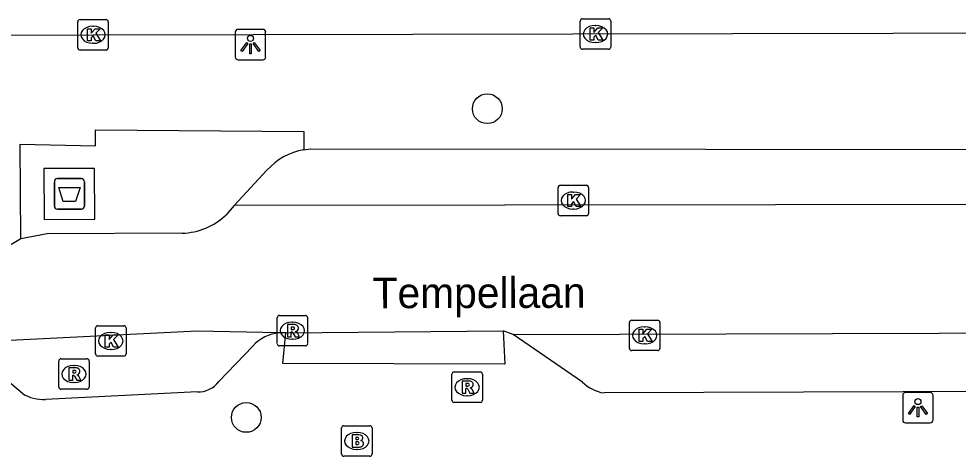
# Model space of a CAD drawing. Extents: x 160732 to 162105, y 387428 to 388479.
# Drawn here: x 161057.8 to 161088.62, y 388326.06 to 388340.41 of the extents above; entities that cross this region are included whole.
import ezdxf

# ---------------------------------------------------------------- set-up
doc = ezdxf.new("R2010")
doc.units = 0
for name, color, linetype in [('IMGEO_Afval_apart_plaats', 7, 'Continuous'), ('IMGEO_Boom', 7, 'Continuous'), ('IMGEO_Brandkraan', 7, 'Continuous'), ('IMGEO_Kolk', 7, 'Continuous'), ('IMGEO_Lichtpunt', 7, 'Continuous'), ('IMGEO_Openbare_ruimte_label', 7, 'Continuous'), ('IMGEO_Parkeervlak_open', 7, 'Continuous'), ('IMGEO_Rijbaan_lokaal_open', 7, 'Continuous'), ('IMGEO_Rijbaan_regionaal_gesloten', 7, 'Continuous'), ('IMGEO_Rioolput', 7, 'Continuous'), ('IMGEO_Voetpad_gesloten', 7, 'Continuous'), ('IMGEO_Voetpad_open', 7, 'Continuous')]:
    doc.layers.add(name, color=color, linetype=linetype)

msp = doc.modelspace()

# ---------------------------------------------------------------- linework, layer by layer
at = {"layer": 'IMGEO_Afval_apart_plaats'}
for p, q in [((161058.967, 388334.266), (161058.967, 388335.066)), ((161058.967, 388335.066), (161058.967, 388334.266)), ((161059.067, 388335.166), (161059.857, 388335.166)), ((161059.857, 388335.166), (161059.067, 388335.166)), ((161059.957, 388335.066), (161059.957, 388334.266)), ((161059.957, 388334.266), (161059.957, 388335.066)), ((161059.857, 388334.166), (161059.067, 388334.166)), ((161059.067, 388334.166), (161059.857, 388334.166))]:
    msp.add_line(p, q, dxfattribs=at)
msp.add_lwpolyline([(161059.11, 388334.88), (161059.814, 388334.88), (161059.665, 388334.41), (161059.259, 388334.41), (161059.11, 388334.88)], dxfattribs=at)
for centre, start, end in [((161059.067, 388335.066), 90, 180), ((161059.067, 388335.066), 90, 180), ((161059.857, 388335.066), 0, 90), ((161059.857, 388335.066), 360, 90), ((161059.067, 388334.266), 180, 270), ((161059.067, 388334.266), 180, 270), ((161059.857, 388334.266), 270, 0), ((161059.857, 388334.266), 270, 0)]:
    msp.add_arc(centre, 0.1, start, end, dxfattribs=at)
at = {"layer": 'IMGEO_Boom'}
for centre in [(161073.173, 388337.461), (161065.264, 388327.33)]:
    msp.add_circle(centre, 0.489, dxfattribs=at)
at = {"layer": 'IMGEO_Brandkraan'}
for p, q in [((161068.39, 388326.131), (161068.39, 388326.983)), ((161068.465, 388327.057), (161069.317, 388327.057)), ((161069.391, 388326.983), (161069.391, 388326.131)), ((161068.878, 388326.837), (161068.903, 388326.837)), ((161069.317, 388326.057), (161068.465, 388326.057)), ((161068.901, 388326.277), (161068.876, 388326.277))]:
    msp.add_line(p, q, dxfattribs=at)
for points in [[(161068.39, 388326.131), (161068.39, 388326.983)], [(161068.465, 388327.057), (161069.317, 388327.057)], [(161069.391, 388326.983), (161069.391, 388326.131)], [(161068.738, 388326.757), (161068.738, 388326.357), (161068.951, 388326.357)], [(161068.969, 388326.757), (161068.738, 388326.757)], [(161068.917, 388326.676), (161068.863, 388326.676), (161068.863, 388326.6)], [(161068.863, 388326.6), (161068.916, 388326.6)], [(161068.925, 388326.524), (161068.863, 388326.524), (161068.863, 388326.443)], [(161068.863, 388326.443), (161068.925, 388326.443)], [(161069.317, 388326.057), (161068.465, 388326.057)]]:
    msp.add_lwpolyline(points, dxfattribs=at)
for centre, radius, start, end in [((161068.467, 388326.981), 0.0765, 91.552, 178.448), ((161068.467, 388326.981), 0.0765, 91.552, 178.448), ((161069.315, 388326.981), 0.0765, 1.552, 88.448), ((161069.315, 388326.981), 0.0765, 1.552, 88.448), ((161068.918, 388326.638), 0.0379, 267.8285, 90.9355), ((161068.973, 388326.612), 0.145, 59.4692, 91.5367), ((161068.998, 388326.659), 0.0922, 285.5137, 58.1501), ((161068.926, 388326.483), 0.0404, 269.8759, 90.5077), ((161068.957, 388326.608), 0.251, 268.6676, 293.5347), ((161069.003, 388326.467), 0.105, 301.3115, 78.989), ((161068.467, 388326.133), 0.0765, 181.552, 268.448), ((161068.467, 388326.133), 0.0765, 181.552, 268.448), ((161069.315, 388326.133), 0.0765, 271.552, 358.448), ((161069.315, 388326.133), 0.0765, 271.552, 358.448)]:
    msp.add_arc(centre, radius, start, end, dxfattribs=at)
for centre, major_axis, ratio, start_param, end_param in [((161068.877, 388326.557), (-0.387, 0.002), 0.722429, 4.712389, 7.853982), ((161068.902, 388326.557), (-0.39, 0.002), 0.717154, 1.570796, 4.712389)]:
    msp.add_ellipse(centre, major_axis=major_axis, ratio=ratio, start_param=start_param, end_param=end_param, dxfattribs=at)
at = {"layer": 'IMGEO_Kolk'}
for p, q in [((161059.735, 388339.461), (161059.735, 388340.313)), ((161059.81, 388340.387), (161060.662, 388340.387)), ((161060.736, 388340.313), (161060.736, 388339.461)), ((161076.221, 388339.485), (161076.221, 388340.337)), ((161076.296, 388340.411), (161077.148, 388340.411)), ((161076.709, 388340.191), (161076.734, 388340.191)), ((161077.222, 388340.337), (161077.222, 388339.485)), ((161060.223, 388340.167), (161060.248, 388340.167)), ((161060.246, 388339.607), (161060.221, 388339.607)), ((161076.732, 388339.631), (161076.707, 388339.631)), ((161060.662, 388339.387), (161059.81, 388339.387)), ((161077.148, 388339.411), (161076.296, 388339.411)), ((161075.57, 388334.946), (161076.422, 388334.946)), ((161075.495, 388334.02), (161075.495, 388334.872)), ((161075.983, 388334.726), (161076.008, 388334.726)), ((161076.496, 388334.872), (161076.496, 388334.02)), ((161076.006, 388334.166), (161075.981, 388334.166)), ((161076.422, 388333.946), (161075.57, 388333.946)), ((161060.393, 388330.34), (161061.245, 388330.34)), ((161077.836, 388329.595), (161077.836, 388330.447)), ((161077.911, 388330.521), (161078.763, 388330.521)), ((161078.837, 388330.447), (161078.837, 388329.595)), ((161060.318, 388329.414), (161060.318, 388330.266)), ((161060.806, 388330.12), (161060.831, 388330.12)), ((161061.319, 388330.266), (161061.319, 388329.414)), ((161078.324, 388330.301), (161078.349, 388330.301)), ((161078.347, 388329.741), (161078.322, 388329.741)), ((161060.829, 388329.56), (161060.804, 388329.56)), ((161078.763, 388329.521), (161077.911, 388329.521)), ((161061.245, 388329.34), (161060.393, 388329.34))]:
    msp.add_line(p, q, dxfattribs=at)
for points in [[(161059.735, 388339.461), (161059.735, 388340.313)], [(161059.81, 388340.387), (161060.662, 388340.387)], [(161060.736, 388340.313), (161060.736, 388339.461)], [(161076.221, 388339.485), (161076.221, 388340.337)], [(161076.296, 388340.411), (161077.148, 388340.411)], [(161077.222, 388340.337), (161077.222, 388339.485)], [(161060.056, 388340.087), (161060.179, 388340.087), (161060.179, 388339.936), (161060.309, 388340.087), (161060.473, 388340.087), (161060.327, 388339.936), (161060.48, 388339.687), (161060.328, 388339.687), (161060.243, 388339.851), (161060.179, 388339.784), (161060.179, 388339.687), (161060.056, 388339.687), (161060.056, 388340.087)], [(161076.542, 388340.111), (161076.665, 388340.111), (161076.665, 388339.96), (161076.795, 388340.111), (161076.959, 388340.111), (161076.813, 388339.96), (161076.966, 388339.711), (161076.814, 388339.711), (161076.729, 388339.875), (161076.665, 388339.808), (161076.665, 388339.711), (161076.542, 388339.711), (161076.542, 388340.111)], [(161060.662, 388339.387), (161059.81, 388339.387)], [(161077.148, 388339.411), (161076.296, 388339.411)], [(161075.57, 388334.946), (161076.422, 388334.946)], [(161075.495, 388334.02), (161075.495, 388334.872)], [(161075.816, 388334.646), (161075.939, 388334.646), (161075.939, 388334.495), (161076.069, 388334.646), (161076.233, 388334.646), (161076.087, 388334.495), (161076.24, 388334.246), (161076.088, 388334.246), (161076.003, 388334.41), (161075.939, 388334.343), (161075.939, 388334.246), (161075.816, 388334.246), (161075.816, 388334.646)], [(161076.496, 388334.872), (161076.496, 388334.02)], [(161076.422, 388333.946), (161075.57, 388333.946)], [(161060.393, 388330.34), (161061.245, 388330.34)], [(161077.836, 388329.595), (161077.836, 388330.447)], [(161077.911, 388330.521), (161078.763, 388330.521)], [(161078.837, 388330.447), (161078.837, 388329.595)], [(161060.318, 388329.414), (161060.318, 388330.266)], [(161060.639, 388330.04), (161060.762, 388330.04), (161060.762, 388329.889), (161060.892, 388330.04), (161061.056, 388330.04), (161060.91, 388329.889), (161061.063, 388329.64), (161060.911, 388329.64), (161060.826, 388329.804), (161060.762, 388329.737), (161060.762, 388329.64), (161060.639, 388329.64), (161060.639, 388330.04)], [(161061.319, 388330.266), (161061.319, 388329.414)], [(161078.157, 388330.221), (161078.28, 388330.221), (161078.28, 388330.07), (161078.41, 388330.221), (161078.574, 388330.221), (161078.428, 388330.07), (161078.581, 388329.821), (161078.429, 388329.821), (161078.344, 388329.985), (161078.28, 388329.918), (161078.28, 388329.821), (161078.157, 388329.821), (161078.157, 388330.221)], [(161078.763, 388329.521), (161077.911, 388329.521)], [(161061.245, 388329.34), (161060.393, 388329.34)]]:
    msp.add_lwpolyline(points, dxfattribs=at)
for centre, start, end in [((161059.812, 388340.311), 91.552, 178.448), ((161059.812, 388340.311), 91.552, 178.448), ((161060.66, 388340.311), 1.552, 88.448), ((161060.66, 388340.311), 1.552, 88.448), ((161076.298, 388340.335), 91.552, 178.448), ((161076.298, 388340.335), 91.552, 178.448), ((161077.146, 388340.335), 1.552, 88.448), ((161077.146, 388340.335), 1.552, 88.448), ((161059.812, 388339.463), 181.552, 268.448), ((161059.812, 388339.463), 181.552, 268.448), ((161060.66, 388339.463), 271.552, 358.448), ((161060.66, 388339.463), 271.552, 358.448), ((161076.298, 388339.487), 181.552, 268.448), ((161076.298, 388339.487), 181.552, 268.448), ((161077.146, 388339.487), 271.552, 358.448), ((161077.146, 388339.487), 271.552, 358.448), ((161075.572, 388334.87), 91.552, 178.448), ((161075.572, 388334.87), 91.552, 178.448), ((161076.42, 388334.87), 1.552, 88.448), ((161076.42, 388334.87), 1.552, 88.448), ((161075.572, 388334.022), 181.552, 268.448), ((161075.572, 388334.022), 181.552, 268.448), ((161076.42, 388334.022), 271.552, 358.448), ((161076.42, 388334.022), 271.552, 358.448), ((161060.395, 388330.264), 91.552, 178.448), ((161060.395, 388330.264), 91.552, 178.448), ((161061.243, 388330.264), 1.552, 88.448), ((161061.243, 388330.264), 1.552, 88.448), ((161077.913, 388330.445), 91.552, 178.448), ((161077.913, 388330.445), 91.552, 178.448), ((161078.761, 388330.445), 1.552, 88.448), ((161078.761, 388330.445), 1.552, 88.448), ((161060.395, 388329.416), 181.552, 268.448), ((161060.395, 388329.416), 181.552, 268.448), ((161061.243, 388329.416), 271.552, 358.448), ((161061.243, 388329.416), 271.552, 358.448), ((161077.913, 388329.597), 181.552, 268.448), ((161077.913, 388329.597), 181.552, 268.448), ((161078.761, 388329.597), 271.552, 358.448), ((161078.761, 388329.597), 271.552, 358.448)]:
    msp.add_arc(centre, 0.0765, start, end, dxfattribs=at)
for centre, major_axis, ratio, start_param, end_param in [((161076.708, 388339.911), (-0.387, 0.002), 0.722429, 4.712389, 7.853982), ((161076.733, 388339.911), (-0.39, 0.002), 0.717154, 1.570796, 4.712389), ((161060.222, 388339.887), (-0.387, 0.002), 0.722429, 4.712389, 7.853982), ((161060.247, 388339.887), (-0.39, 0.002), 0.717154, 1.570796, 4.712389), ((161075.982, 388334.446), (-0.387, 0.002), 0.722429, 4.712389, 7.853982), ((161076.007, 388334.446), (-0.39, 0.002), 0.717154, 1.570796, 4.712389), ((161060.805, 388329.84), (-0.387, 0.002), 0.722429, 4.712389, 7.853982), ((161060.83, 388329.84), (-0.39, 0.002), 0.717154, 1.570796, 4.712389), ((161078.323, 388330.021), (-0.387, 0.002), 0.722429, 4.712389, 7.853982), ((161078.348, 388330.021), (-0.39, 0.002), 0.717154, 1.570796, 4.712389)]:
    msp.add_ellipse(centre, major_axis=major_axis, ratio=ratio, start_param=start_param, end_param=end_param, dxfattribs=at)
at = {"layer": 'IMGEO_Lichtpunt'}
for p, q in [((161064.904, 388339.968), (161064.904, 388339.161)), ((161064.904, 388339.968), (161064.904, 388339.161)), ((161065.806, 388340.063), (161064.998, 388340.063)), ((161065.806, 388340.063), (161064.998, 388340.063)), ((161065.9, 388339.161), (161065.9, 388339.968)), ((161065.9, 388339.161), (161065.9, 388339.968)), ((161064.998, 388339.067), (161065.806, 388339.067)), ((161064.998, 388339.067), (161065.806, 388339.067)), ((161086.802, 388328.052), (161086.802, 388327.245)), ((161086.802, 388328.052), (161086.802, 388327.245)), ((161087.704, 388328.147), (161086.896, 388328.147)), ((161087.704, 388328.147), (161086.896, 388328.147)), ((161087.798, 388327.245), (161087.798, 388328.052)), ((161087.798, 388327.245), (161087.798, 388328.052)), ((161086.896, 388327.151), (161087.704, 388327.151)), ((161086.896, 388327.151), (161087.704, 388327.151))]:
    msp.add_line(p, q, dxfattribs=at)
for points in [[(161065.278, 388339.632), (161065.317, 388339.604), (161065.129, 388339.342), (161065.091, 388339.369), (161065.278, 388339.632)], [(161065.38, 388339.584), (161065.427, 388339.584), (161065.427, 388339.262), (161065.38, 388339.262), (161065.38, 388339.584)], [(161065.49, 388339.604), (161065.528, 388339.631), (161065.715, 388339.369), (161065.676, 388339.341), (161065.49, 388339.604)], [(161087.176, 388327.716), (161087.215, 388327.688), (161087.027, 388327.426), (161086.989, 388327.453), (161087.176, 388327.716)], [(161087.278, 388327.668), (161087.325, 388327.668), (161087.325, 388327.346), (161087.278, 388327.346), (161087.278, 388327.668)], [(161087.388, 388327.688), (161087.426, 388327.715), (161087.613, 388327.453), (161087.574, 388327.425), (161087.388, 388327.688)]]:
    msp.add_lwpolyline(points, dxfattribs=at)
for centre in [(161065.403, 388339.766), (161087.301, 388327.85)]:
    msp.add_circle(centre, 0.0994, dxfattribs=at)
for centre, start, end in [((161064.998, 388339.968), 90, 180), ((161064.998, 388339.968), 90, 180), ((161065.806, 388339.968), 0, 90), ((161065.806, 388339.968), 0, 90), ((161064.998, 388339.161), 180, 270), ((161064.998, 388339.161), 180, 270), ((161065.806, 388339.161), 270, 0), ((161065.806, 388339.161), 270, 360), ((161086.896, 388328.052), 90, 180), ((161086.896, 388328.052), 90, 180), ((161087.704, 388328.052), 0, 90), ((161087.704, 388328.052), 0, 90), ((161086.896, 388327.245), 180, 270), ((161086.896, 388327.245), 180, 270), ((161087.704, 388327.245), 270, 0), ((161087.704, 388327.245), 270, 360)]:
    msp.add_arc(centre, 0.0946, start, end, dxfattribs=at)
at = {"layer": 'IMGEO_Parkeervlak_open'}
msp.add_lwpolyline([(161067.152, 388336.115), (161067.357, 388336.139), (161106.269, 388336.114)], dxfattribs=at)
at = {"layer": 'IMGEO_Rijbaan_lokaal_open'}
for points in [[(161109.259, 388334.338), (161064.865, 388334.284)], [(161064.865, 388334.284), (161064.601, 388333.978)], [(161057.87, 388333.189), (161057.295, 388332.853)], [(161063.16, 388333.374), (161058.732, 388333.358), (161057.87, 388333.189)], [(161066.347, 388330.105), (161063.655, 388330.157), (161055.964, 388329.781)], [(161066.562, 388330.109), (161066.347, 388330.105)], [(161066.562, 388330.109), (161073.696, 388330.176)], [(161074.021, 388330.052), (161073.696, 388330.176)], [(161074.021, 388330.052), (161119.444, 388330.198)]]:
    msp.add_lwpolyline(points, dxfattribs=at)
msp.add_arc((161063.084, 388335.575), 2.203, 271.9681, 313.5142, dxfattribs=at)
at = {"layer": 'IMGEO_Rijbaan_regionaal_gesloten'}
msp.add_lwpolyline([(161054.982, 388339.878), (161144.197, 388340.064)], dxfattribs=at)
at = {"layer": 'IMGEO_Rioolput'}
for p, q in [((161066.352, 388330.676), (161067.204, 388330.676)), ((161066.277, 388329.75), (161066.277, 388330.602)), ((161066.765, 388330.456), (161066.79, 388330.456)), ((161067.278, 388330.602), (161067.278, 388329.75)), ((161066.788, 388329.896), (161066.763, 388329.896)), ((161067.204, 388329.676), (161066.352, 388329.676)), ((161059.11, 388328.329), (161059.11, 388329.181)), ((161059.185, 388329.255), (161060.037, 388329.255)), ((161060.111, 388329.181), (161060.111, 388328.329)), ((161059.598, 388329.035), (161059.623, 388329.035)), ((161072.085, 388328.821), (161072.937, 388328.821)), ((161059.621, 388328.475), (161059.596, 388328.475)), ((161072.01, 388327.895), (161072.01, 388328.747)), ((161072.498, 388328.601), (161072.523, 388328.601)), ((161073.011, 388328.747), (161073.011, 388327.895)), ((161060.037, 388328.255), (161059.185, 388328.255)), ((161072.521, 388328.041), (161072.496, 388328.041)), ((161072.937, 388327.821), (161072.085, 388327.821))]:
    msp.add_line(p, q, dxfattribs=at)
for points in [[(161066.352, 388330.676), (161067.204, 388330.676)], [(161066.277, 388329.75), (161066.277, 388330.602)], [(161066.866, 388330.374), (161066.614, 388330.376), (161066.614, 388329.976)], [(161067.278, 388330.602), (161067.278, 388329.75)], [(161066.614, 388329.976), (161066.738, 388329.976), (161066.738, 388330.138), (161066.749, 388330.138)], [(161066.792, 388330.295), (161066.738, 388330.295), (161066.738, 388330.214)], [(161066.738, 388330.214), (161066.79, 388330.214)], [(161066.796, 388330.109), (161066.867, 388329.976), (161067.007, 388329.976), (161066.942, 388330.102)], [(161067.204, 388329.676), (161066.352, 388329.676)], [(161059.11, 388328.329), (161059.11, 388329.181)], [(161059.185, 388329.255), (161060.037, 388329.255)], [(161060.111, 388329.181), (161060.111, 388328.329)], [(161059.699, 388328.953), (161059.447, 388328.955), (161059.447, 388328.555)], [(161059.625, 388328.874), (161059.571, 388328.874), (161059.571, 388328.793)], [(161059.571, 388328.793), (161059.623, 388328.793)], [(161072.085, 388328.821), (161072.937, 388328.821)], [(161059.447, 388328.555), (161059.571, 388328.555), (161059.571, 388328.717), (161059.582, 388328.717)], [(161059.629, 388328.688), (161059.7, 388328.555), (161059.84, 388328.555), (161059.775, 388328.681)], [(161072.01, 388327.895), (161072.01, 388328.747)], [(161072.599, 388328.519), (161072.347, 388328.521), (161072.347, 388328.121)], [(161073.011, 388328.747), (161073.011, 388327.895)], [(161060.037, 388328.255), (161059.185, 388328.255)], [(161072.347, 388328.121), (161072.471, 388328.121), (161072.471, 388328.283), (161072.482, 388328.283)], [(161072.525, 388328.44), (161072.471, 388328.44), (161072.471, 388328.359)], [(161072.471, 388328.359), (161072.523, 388328.359)], [(161072.529, 388328.254), (161072.6, 388328.121), (161072.74, 388328.121), (161072.675, 388328.247)], [(161072.937, 388327.821), (161072.085, 388327.821)]]:
    msp.add_lwpolyline(points, dxfattribs=at)
for centre, radius, start, end in [((161066.354, 388330.6), 0.0765, 91.552, 178.448), ((161066.354, 388330.6), 0.0765, 91.552, 178.448), ((161067.202, 388330.6), 0.0765, 1.552, 88.448), ((161067.202, 388330.6), 0.0765, 1.552, 88.448), ((161066.865, 388330.264), 0.109, 350.3612, 89.416), ((161066.748, 388330.085), 0.0533, 26.0293, 88.6989), ((161066.774, 388330.403), 0.19, 274.7715, 282.9687), ((161066.798, 388330.199), 0.0964, 77.0061, 93.1865), ((161066.812, 388330.256), 0.0378, 276.6634, 79.6772), ((161066.863, 388330.264), 0.112, 277.5842, 350.9817), ((161066.847, 388330.049), 0.108, 29.5134, 73.7905), ((161066.354, 388329.752), 0.0765, 181.552, 268.448), ((161066.354, 388329.752), 0.0765, 181.552, 268.448), ((161067.202, 388329.752), 0.0765, 271.552, 358.448), ((161067.202, 388329.752), 0.0765, 271.552, 358.448), ((161059.187, 388329.179), 0.0765, 91.552, 178.448), ((161059.187, 388329.179), 0.0765, 91.552, 178.448), ((161060.035, 388329.179), 0.0765, 1.552, 88.448), ((161060.035, 388329.179), 0.0765, 1.552, 88.448), ((161059.607, 388328.982), 0.19, 274.7715, 282.9687), ((161059.631, 388328.778), 0.0964, 77.0061, 93.1865), ((161059.645, 388328.835), 0.0378, 276.6634, 79.6772), ((161059.698, 388328.843), 0.109, 350.3612, 89.416), ((161059.696, 388328.843), 0.112, 277.5842, 350.9817), ((161072.087, 388328.745), 0.0765, 91.552, 178.448), ((161072.087, 388328.745), 0.0765, 91.552, 178.448), ((161072.935, 388328.745), 0.0765, 1.552, 88.448), ((161072.935, 388328.745), 0.0765, 1.552, 88.448), ((161059.581, 388328.664), 0.0533, 26.0293, 88.6989), ((161059.68, 388328.628), 0.108, 29.5134, 73.7905), ((161072.598, 388328.409), 0.109, 350.3612, 89.416), ((161059.187, 388328.331), 0.0765, 181.552, 268.448), ((161059.187, 388328.331), 0.0765, 181.552, 268.448), ((161060.035, 388328.331), 0.0765, 271.552, 358.448), ((161060.035, 388328.331), 0.0765, 271.552, 358.448), ((161072.481, 388328.23), 0.0533, 26.0293, 88.6989), ((161072.507, 388328.548), 0.19, 274.7715, 282.9687), ((161072.531, 388328.344), 0.0964, 77.0061, 93.1865), ((161072.545, 388328.401), 0.0378, 276.6634, 79.6772), ((161072.596, 388328.409), 0.112, 277.5842, 350.9817), ((161072.58, 388328.194), 0.108, 29.5134, 73.7905), ((161072.087, 388327.897), 0.0765, 181.552, 268.448), ((161072.087, 388327.897), 0.0765, 181.552, 268.448), ((161072.935, 388327.897), 0.0765, 271.552, 358.448), ((161072.935, 388327.897), 0.0765, 271.552, 358.448)]:
    msp.add_arc(centre, radius, start, end, dxfattribs=at)
for centre, major_axis, ratio, start_param, end_param in [((161066.764, 388330.176), (-0.387, 0.002), 0.722429, 4.712389, 7.853982), ((161066.789, 388330.176), (-0.39, 0.002), 0.717154, 1.570796, 4.712389), ((161059.597, 388328.755), (-0.387, 0.002), 0.722429, 4.712389, 7.853982), ((161059.622, 388328.755), (-0.39, 0.002), 0.717154, 1.570796, 4.712389), ((161072.497, 388328.321), (-0.387, 0.002), 0.722429, 4.712389, 7.853982), ((161072.522, 388328.321), (-0.39, 0.002), 0.717154, 1.570796, 4.712389)]:
    msp.add_ellipse(centre, major_axis=major_axis, ratio=ratio, start_param=start_param, end_param=end_param, dxfattribs=at)
at = {"layer": 'IMGEO_Voetpad_gesloten'}
msp.add_lwpolyline([(161060.289, 388335.503), (161058.626, 388335.493), (161058.636, 388333.829), (161060.299, 388333.839), (161060.289, 388335.503)], dxfattribs=at)
at = {"layer": 'IMGEO_Voetpad_open'}
for points in [[(161057.87, 388333.189), (161057.85, 388336.295), (161060.318, 388336.24), (161060.313, 388336.766), (161067.152, 388336.715), (161067.152, 388336.115)], [(161065.943, 388335.44), (161064.865, 388334.284)], [(161073.696, 388330.176), (161073.748, 388329.073), (161066.464, 388329.094), (161066.562, 388330.109)], [(161076.293, 388328.485), (161074.021, 388330.052)], [(161065.476, 388329.673), (161064.365, 388328.505)], [(161057.921, 388328.111), (161056.582, 388329.244)], [(161063.662, 388328.164), (161058.672, 388327.919)], [(161116.222, 388328.269), (161077.001, 388328.134)]]:
    msp.add_lwpolyline(points, dxfattribs=at)
for centre, radius, start, end in [((161067.501, 388334.069), 2.075, 99.6877, 138.6627), ((161066.471, 388328.761), 1.35, 95.2752, 137.486), ((161063.671, 388329.04), 0.876, 269.4004, 322.3523), ((161077.191, 388329.407), 1.287, 225.7479, 261.5111), ((161058.617, 388329.267), 1.349, 238.9616, 272.3563)]:
    msp.add_arc(centre, radius, start, end, dxfattribs=at)

# ---------------------------------------------------------------- texts
at = {"layer": 'IMGEO_Openbare_ruimte_label'}
msp.add_text('Tempellaan', height=1, rotation=0.1146, dxfattribs=at).set_placement((161069.41, 388330.914))

doc.saveas('drawing.dxf')
